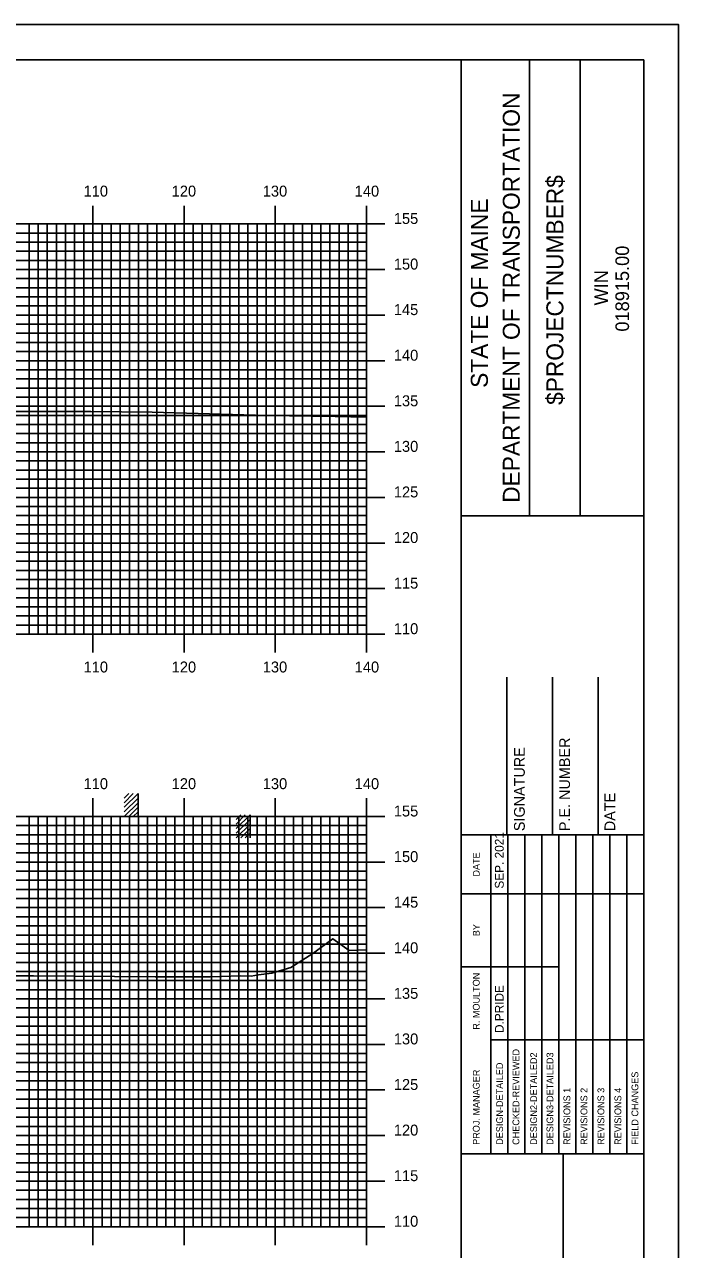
# Model space of a CAD drawing. Extents: x 1770448 to 1770792, y 442591 to 442811.
# Drawn here: x 1770716.5 to 1770788.3, y 442676.2 to 442810.5 of the extents above; entities that cross this region are included whole.
import ezdxf

# ---------------------------------------------------------------- set-up
doc = ezdxf.new("R2010")
doc.units = 0
for name, color, linetype in [('BORDER', 7, 'Continuous'), ('H_V ANNOTATION', 7, 'Continuous'), ('M_Buildings_Rooftop', 7, 'Continuous'), ('MAJOR', 7, 'Continuous'), ('MINOR', 7, 'Continuous'), ('PLOT BOUNDARY', 7, 'Continuous'), ('S_Roadway_Centerline', 7, 'Continuous')]:
    doc.layers.add(name, color=color, linetype=linetype)

msp = doc.modelspace()

# ---------------------------------------------------------------- linework, layer by layer
at = {"layer": 'BORDER'}
for p, q in [((1770764.44, 442596.67), (1770764.44, 442806.67)), ((1770771.9, 442756.66), (1770771.9, 442806.66)), ((1770777.49, 442756.66), (1770777.49, 442806.66)), ((1770764.44, 442756.65), (1770784.44, 442756.65)), ((1770769.44, 442721.67), (1770769.44, 442738.97)), ((1770774.44, 442721.67), (1770774.44, 442738.97)), ((1770779.44, 442721.67), (1770779.44, 442738.97)), ((1770764.44, 442721.67), (1770784.44, 442721.67)), ((1770764.44, 442686.67), (1770784.44, 442686.67)), ((1770775.62, 442616.67), (1770775.62, 442686.67))]:
    msp.add_line(p, q, dxfattribs=at)
msp.add_lwpolyline([(1770464.44, 442596.67), (1770784.44, 442596.67), (1770784.44, 442806.67), (1770464.44, 442806.67)], close=True, dxfattribs=at)
for points in [[(1770767.67, 442715.17), (1770767.67, 442721.67)], [(1770769.54, 442686.68), (1770769.54, 442721.67)], [(1770771.4, 442721.67), (1770771.4, 442686.68)], [(1770773.26, 442686.68), (1770773.26, 442721.67)], [(1770775.13, 442686.68), (1770775.13, 442721.67)], [(1770776.99, 442686.68), (1770776.99, 442721.67)], [(1770778.85, 442686.68), (1770778.85, 442721.67)], [(1770780.72, 442686.68), (1770780.72, 442721.67)], [(1770782.58, 442686.68), (1770782.58, 442721.67)], [(1770767.67, 442686.68), (1770767.67, 442720.26)], [(1770764.44, 442715.17), (1770784.44, 442715.17)], [(1770764.44, 442707.17), (1770767.67, 442707.17)], [(1770767.67, 442707.17), (1770775.12, 442707.17)], [(1770767.67, 442699.17), (1770784.44, 442699.17)]]:
    msp.add_lwpolyline(points, dxfattribs=at)
at = {"layer": 'M_Buildings_Rooftop'}
for p, q in [((1770727.48, 442724.68), (1770728.99, 442726.19)), ((1770727.48, 442725.17), (1770728.47, 442726.19)), ((1770727.48, 442725.67), (1770727.97, 442726.19)), ((1770728.99, 442723.67), (1770728.99, 442726.19)), ((1770727.48, 442724.19), (1770728.99, 442725.67)), ((1770727.48, 442723.67), (1770728.99, 442725.17)), ((1770727.97, 442723.67), (1770728.99, 442724.68)), ((1770728.47, 442723.67), (1770728.99, 442724.19)), ((1770739.76, 442722.34), (1770741.27, 442723.85)), ((1770739.76, 442722.84), (1770740.75, 442723.85)), ((1770739.76, 442723.33), (1770740.26, 442723.85)), ((1770739.76, 442721.85), (1770741.27, 442723.33)), ((1770741.27, 442721.33), (1770741.27, 442723.85)), ((1770739.76, 442721.33), (1770741.27, 442722.84)), ((1770740.26, 442721.33), (1770741.27, 442722.34)), ((1770740.75, 442721.33), (1770741.27, 442721.85))]:
    msp.add_line(p, q, dxfattribs=at)
at = {"layer": 'MAJOR'}
for p, q in [((1770724.04, 442790.67), (1770724.04, 442788.67)), ((1770734.04, 442790.67), (1770734.04, 442788.67)), ((1770744.04, 442790.67), (1770744.04, 442788.67)), ((1770754.04, 442790.67), (1770754.04, 442788.67)), ((1770474.04, 442788.67), (1770754.04, 442788.67)), ((1770474.04, 442788.67), (1770754.04, 442788.67)), ((1770724.04, 442743.67), (1770724.04, 442788.67)), ((1770734.04, 442743.67), (1770734.04, 442788.67)), ((1770744.04, 442743.67), (1770744.04, 442788.67)), ((1770756.05, 442788.67), (1770752.04, 442788.67)), ((1770754.04, 442743.67), (1770754.04, 442788.67)), ((1770754.04, 442743.67), (1770754.04, 442788.67)), ((1770474.04, 442783.67), (1770754.04, 442783.67)), ((1770756.05, 442783.67), (1770752.04, 442783.67)), ((1770474.04, 442778.67), (1770754.04, 442778.67)), ((1770756.05, 442778.67), (1770752.04, 442778.67)), ((1770474.04, 442773.67), (1770754.04, 442773.67)), ((1770756.05, 442773.67), (1770752.04, 442773.67)), ((1770474.04, 442768.67), (1770754.04, 442768.67)), ((1770756.05, 442768.67), (1770752.04, 442768.67)), ((1770474.04, 442763.67), (1770754.04, 442763.67)), ((1770756.05, 442763.67), (1770752.04, 442763.67)), ((1770474.04, 442758.67), (1770754.04, 442758.67)), ((1770756.05, 442758.67), (1770752.04, 442758.67)), ((1770474.04, 442753.67), (1770754.04, 442753.67)), ((1770756.05, 442753.67), (1770752.04, 442753.67)), ((1770474.04, 442748.67), (1770754.04, 442748.67)), ((1770756.05, 442748.67), (1770752.04, 442748.67)), ((1770474.04, 442743.67), (1770754.04, 442743.67)), ((1770474.04, 442743.67), (1770754.04, 442743.67)), ((1770724.04, 442741.66), (1770724.04, 442743.67)), ((1770734.04, 442741.66), (1770734.04, 442743.67)), ((1770744.04, 442741.66), (1770744.04, 442743.67)), ((1770756.05, 442743.67), (1770752.04, 442743.67)), ((1770754.04, 442741.66), (1770754.04, 442743.67)), ((1770724.04, 442725.67), (1770724.04, 442723.67)), ((1770734.04, 442725.67), (1770734.04, 442723.67)), ((1770744.04, 442725.67), (1770744.04, 442723.67)), ((1770754.04, 442725.67), (1770754.04, 442723.67)), ((1770474.04, 442723.67), (1770754.04, 442723.67)), ((1770474.04, 442723.67), (1770754.04, 442723.67)), ((1770724.04, 442678.67), (1770724.04, 442723.67)), ((1770734.04, 442678.67), (1770734.04, 442723.67)), ((1770744.04, 442678.67), (1770744.04, 442723.67)), ((1770756.05, 442723.67), (1770752.04, 442723.67)), ((1770754.04, 442678.67), (1770754.04, 442723.67)), ((1770754.04, 442678.67), (1770754.04, 442723.67)), ((1770474.04, 442718.67), (1770754.04, 442718.67)), ((1770756.05, 442718.67), (1770752.04, 442718.67)), ((1770474.04, 442713.67), (1770754.04, 442713.67)), ((1770756.05, 442713.67), (1770752.04, 442713.67)), ((1770474.04, 442708.67), (1770754.04, 442708.67)), ((1770756.05, 442708.67), (1770752.04, 442708.67)), ((1770474.04, 442703.67), (1770754.04, 442703.67)), ((1770756.05, 442703.67), (1770752.04, 442703.67)), ((1770474.04, 442698.67), (1770754.04, 442698.67)), ((1770756.05, 442698.67), (1770752.04, 442698.67)), ((1770474.04, 442693.67), (1770754.04, 442693.67)), ((1770756.05, 442693.67), (1770752.04, 442693.67)), ((1770474.04, 442688.67), (1770754.04, 442688.67)), ((1770756.05, 442688.67), (1770752.04, 442688.67)), ((1770474.04, 442683.67), (1770754.04, 442683.67)), ((1770756.05, 442683.67), (1770752.04, 442683.67)), ((1770474.04, 442678.67), (1770754.04, 442678.67)), ((1770474.04, 442678.67), (1770754.04, 442678.67)), ((1770724.04, 442676.66), (1770724.04, 442678.67)), ((1770734.04, 442676.66), (1770734.04, 442678.67)), ((1770744.04, 442676.66), (1770744.04, 442678.67)), ((1770756.05, 442678.67), (1770752.04, 442678.67)), ((1770754.04, 442676.66), (1770754.04, 442678.67))]:
    msp.add_line(p, q, dxfattribs=at)
at = {"layer": 'MINOR'}
for p, q in [((1770717.04, 442743.67), (1770717.04, 442788.67)), ((1770718.04, 442743.67), (1770718.04, 442788.67)), ((1770719.04, 442743.67), (1770719.04, 442788.67)), ((1770720.04, 442743.67), (1770720.04, 442788.67)), ((1770721.04, 442743.67), (1770721.04, 442788.67)), ((1770722.04, 442743.67), (1770722.04, 442788.67)), ((1770723.04, 442743.67), (1770723.04, 442788.67)), ((1770725.04, 442743.67), (1770725.04, 442788.67)), ((1770726.04, 442743.67), (1770726.04, 442788.67)), ((1770727.04, 442743.67), (1770727.04, 442788.67)), ((1770728.04, 442743.67), (1770728.04, 442788.67)), ((1770729.04, 442743.67), (1770729.04, 442788.67)), ((1770730.04, 442743.67), (1770730.04, 442788.67)), ((1770731.04, 442743.67), (1770731.04, 442788.67)), ((1770732.04, 442743.67), (1770732.04, 442788.67)), ((1770733.04, 442743.67), (1770733.04, 442788.67)), ((1770735.04, 442743.67), (1770735.04, 442788.67)), ((1770736.04, 442743.67), (1770736.04, 442788.67)), ((1770737.04, 442743.67), (1770737.04, 442788.67)), ((1770738.04, 442743.67), (1770738.04, 442788.67)), ((1770739.04, 442743.67), (1770739.04, 442788.67)), ((1770740.04, 442743.67), (1770740.04, 442788.67)), ((1770741.04, 442743.67), (1770741.04, 442788.67)), ((1770742.04, 442743.67), (1770742.04, 442788.67)), ((1770743.04, 442743.67), (1770743.04, 442788.67)), ((1770745.04, 442743.67), (1770745.04, 442788.67)), ((1770746.04, 442743.67), (1770746.04, 442788.67)), ((1770747.04, 442743.67), (1770747.04, 442788.67)), ((1770748.04, 442743.67), (1770748.04, 442788.67)), ((1770749.04, 442743.67), (1770749.04, 442788.67)), ((1770750.04, 442743.67), (1770750.04, 442788.67)), ((1770751.04, 442743.67), (1770751.04, 442788.67)), ((1770752.04, 442743.67), (1770752.04, 442788.67)), ((1770753.04, 442743.67), (1770753.04, 442788.67)), ((1770474.04, 442787.67), (1770754.04, 442787.67)), ((1770474.04, 442786.67), (1770754.04, 442786.67)), ((1770754.04, 442787.67), (1770752.04, 442787.67)), ((1770754.04, 442786.67), (1770752.04, 442786.67)), ((1770474.04, 442785.67), (1770754.04, 442785.67)), ((1770754.04, 442785.67), (1770752.04, 442785.67)), ((1770474.04, 442784.67), (1770754.04, 442784.67)), ((1770754.04, 442784.67), (1770752.04, 442784.67)), ((1770474.04, 442782.67), (1770754.04, 442782.67)), ((1770754.04, 442782.67), (1770752.04, 442782.67)), ((1770474.04, 442781.67), (1770754.04, 442781.67)), ((1770754.04, 442781.67), (1770752.04, 442781.67)), ((1770474.04, 442780.67), (1770754.04, 442780.67)), ((1770474.04, 442779.67), (1770754.04, 442779.67)), ((1770754.04, 442780.67), (1770752.04, 442780.67)), ((1770754.04, 442779.67), (1770752.04, 442779.67)), ((1770474.04, 442777.67), (1770754.04, 442777.67)), ((1770754.04, 442777.67), (1770752.04, 442777.67)), ((1770474.04, 442776.67), (1770754.04, 442776.67)), ((1770474.04, 442775.67), (1770754.04, 442775.67)), ((1770754.04, 442776.67), (1770752.04, 442776.67)), ((1770754.04, 442775.67), (1770752.04, 442775.67)), ((1770474.04, 442774.67), (1770754.04, 442774.67)), ((1770754.04, 442774.67), (1770752.04, 442774.67)), ((1770474.04, 442772.67), (1770754.04, 442772.67)), ((1770474.04, 442771.67), (1770754.04, 442771.67)), ((1770754.04, 442772.67), (1770752.04, 442772.67)), ((1770754.04, 442771.67), (1770752.04, 442771.67)), ((1770474.04, 442770.67), (1770754.04, 442770.67)), ((1770754.04, 442770.67), (1770752.04, 442770.67)), ((1770474.04, 442769.67), (1770754.04, 442769.67)), ((1770754.04, 442769.67), (1770752.04, 442769.67)), ((1770474.04, 442767.67), (1770754.04, 442767.67)), ((1770754.04, 442767.67), (1770752.04, 442767.67)), ((1770474.04, 442766.67), (1770754.04, 442766.67)), ((1770754.04, 442766.67), (1770752.04, 442766.67)), ((1770474.04, 442765.67), (1770754.04, 442765.67)), ((1770754.04, 442765.67), (1770752.04, 442765.67)), ((1770474.04, 442764.67), (1770754.04, 442764.67)), ((1770754.04, 442764.67), (1770752.04, 442764.67)), ((1770474.04, 442762.67), (1770754.04, 442762.67)), ((1770754.04, 442762.67), (1770752.04, 442762.67)), ((1770474.04, 442761.67), (1770754.04, 442761.67)), ((1770754.04, 442761.67), (1770752.04, 442761.67)), ((1770474.04, 442760.67), (1770754.04, 442760.67)), ((1770474.04, 442759.67), (1770754.04, 442759.67)), ((1770754.04, 442760.67), (1770752.04, 442760.67)), ((1770754.04, 442759.67), (1770752.04, 442759.67)), ((1770474.04, 442757.67), (1770754.04, 442757.67)), ((1770754.04, 442757.67), (1770752.04, 442757.67)), ((1770474.04, 442756.67), (1770754.04, 442756.67)), ((1770474.04, 442755.67), (1770754.04, 442755.67)), ((1770754.04, 442756.67), (1770752.04, 442756.67)), ((1770754.04, 442755.67), (1770752.04, 442755.67)), ((1770474.04, 442754.67), (1770754.04, 442754.67)), ((1770754.04, 442754.67), (1770752.04, 442754.67)), ((1770474.04, 442752.67), (1770754.04, 442752.67)), ((1770474.04, 442751.67), (1770754.04, 442751.67)), ((1770754.04, 442752.67), (1770752.04, 442752.67)), ((1770754.04, 442751.67), (1770752.04, 442751.67)), ((1770474.04, 442750.67), (1770754.04, 442750.67)), ((1770754.04, 442750.67), (1770752.04, 442750.67)), ((1770474.04, 442749.67), (1770754.04, 442749.67)), ((1770754.04, 442749.67), (1770752.04, 442749.67)), ((1770474.04, 442747.67), (1770754.04, 442747.67)), ((1770754.04, 442747.67), (1770752.04, 442747.67)), ((1770474.04, 442746.67), (1770754.04, 442746.67)), ((1770754.04, 442746.67), (1770752.04, 442746.67)), ((1770474.04, 442745.67), (1770754.04, 442745.67)), ((1770754.04, 442745.67), (1770752.04, 442745.67)), ((1770474.04, 442744.67), (1770754.04, 442744.67)), ((1770754.04, 442744.67), (1770752.04, 442744.67)), ((1770717.04, 442678.67), (1770717.04, 442723.67)), ((1770718.04, 442678.67), (1770718.04, 442723.67)), ((1770719.04, 442678.67), (1770719.04, 442723.67)), ((1770720.04, 442678.67), (1770720.04, 442723.67)), ((1770721.04, 442678.67), (1770721.04, 442723.67)), ((1770722.04, 442678.67), (1770722.04, 442723.67)), ((1770723.04, 442678.67), (1770723.04, 442723.67)), ((1770725.04, 442678.67), (1770725.04, 442723.67)), ((1770726.04, 442678.67), (1770726.04, 442723.67)), ((1770727.04, 442678.67), (1770727.04, 442723.67)), ((1770728.04, 442678.67), (1770728.04, 442723.67)), ((1770729.04, 442678.67), (1770729.04, 442723.67)), ((1770730.04, 442678.67), (1770730.04, 442723.67)), ((1770731.04, 442678.67), (1770731.04, 442723.67)), ((1770732.04, 442678.67), (1770732.04, 442723.67)), ((1770733.04, 442678.67), (1770733.04, 442723.67)), ((1770735.04, 442678.67), (1770735.04, 442723.67)), ((1770736.04, 442678.67), (1770736.04, 442723.67)), ((1770737.04, 442678.67), (1770737.04, 442723.67)), ((1770738.04, 442678.67), (1770738.04, 442723.67)), ((1770739.04, 442678.67), (1770739.04, 442723.67)), ((1770740.04, 442678.67), (1770740.04, 442723.67)), ((1770741.04, 442678.67), (1770741.04, 442723.67)), ((1770742.04, 442678.67), (1770742.04, 442723.67)), ((1770743.04, 442678.67), (1770743.04, 442723.67)), ((1770745.04, 442678.67), (1770745.04, 442723.67)), ((1770746.04, 442678.67), (1770746.04, 442723.67)), ((1770747.04, 442678.67), (1770747.04, 442723.67)), ((1770748.04, 442678.67), (1770748.04, 442723.67)), ((1770749.04, 442678.67), (1770749.04, 442723.67)), ((1770750.04, 442678.67), (1770750.04, 442723.67)), ((1770751.04, 442678.67), (1770751.04, 442723.67)), ((1770752.04, 442678.67), (1770752.04, 442723.67)), ((1770753.04, 442678.67), (1770753.04, 442723.67)), ((1770474.04, 442722.67), (1770754.04, 442722.67)), ((1770754.04, 442722.67), (1770752.04, 442722.67)), ((1770474.04, 442721.67), (1770754.04, 442721.67)), ((1770474.04, 442720.67), (1770754.04, 442720.67)), ((1770754.04, 442721.67), (1770752.04, 442721.67)), ((1770754.04, 442720.67), (1770752.04, 442720.67)), ((1770474.04, 442719.67), (1770754.04, 442719.67)), ((1770754.04, 442719.67), (1770752.04, 442719.67)), ((1770474.04, 442717.67), (1770754.04, 442717.67)), ((1770474.04, 442716.67), (1770754.04, 442716.67)), ((1770754.04, 442717.67), (1770752.04, 442717.67)), ((1770754.04, 442716.67), (1770752.04, 442716.67)), ((1770474.04, 442715.67), (1770754.04, 442715.67)), ((1770754.04, 442715.67), (1770752.04, 442715.67)), ((1770474.04, 442714.67), (1770754.04, 442714.67)), ((1770754.04, 442714.67), (1770752.04, 442714.67)), ((1770474.04, 442712.67), (1770754.04, 442712.67)), ((1770754.04, 442712.67), (1770752.04, 442712.67)), ((1770474.04, 442711.67), (1770754.04, 442711.67)), ((1770754.04, 442711.67), (1770752.04, 442711.67)), ((1770474.04, 442710.67), (1770754.04, 442710.67)), ((1770754.04, 442710.67), (1770752.04, 442710.67)), ((1770474.04, 442709.67), (1770754.04, 442709.67)), ((1770754.04, 442709.67), (1770752.04, 442709.67)), ((1770474.04, 442707.67), (1770754.04, 442707.67)), ((1770754.04, 442707.67), (1770752.04, 442707.67)), ((1770474.04, 442706.67), (1770754.04, 442706.67)), ((1770754.04, 442706.67), (1770752.04, 442706.67)), ((1770474.04, 442705.67), (1770754.04, 442705.67)), ((1770474.04, 442704.67), (1770754.04, 442704.67)), ((1770754.04, 442705.67), (1770752.04, 442705.67)), ((1770754.04, 442704.67), (1770752.04, 442704.67)), ((1770474.04, 442702.67), (1770754.04, 442702.67)), ((1770754.04, 442702.67), (1770752.04, 442702.67)), ((1770474.04, 442701.67), (1770754.04, 442701.67)), ((1770474.04, 442700.67), (1770754.04, 442700.67)), ((1770754.04, 442701.67), (1770752.04, 442701.67)), ((1770754.04, 442700.67), (1770752.04, 442700.67)), ((1770474.04, 442699.67), (1770754.04, 442699.67)), ((1770754.04, 442699.67), (1770752.04, 442699.67)), ((1770474.04, 442697.67), (1770754.04, 442697.67)), ((1770474.04, 442696.67), (1770754.04, 442696.67)), ((1770754.04, 442697.67), (1770752.04, 442697.67)), ((1770754.04, 442696.67), (1770752.04, 442696.67)), ((1770474.04, 442695.67), (1770754.04, 442695.67)), ((1770754.04, 442695.67), (1770752.04, 442695.67)), ((1770474.04, 442694.67), (1770754.04, 442694.67)), ((1770754.04, 442694.67), (1770752.04, 442694.67)), ((1770474.04, 442692.67), (1770754.04, 442692.67)), ((1770754.04, 442692.67), (1770752.04, 442692.67)), ((1770474.04, 442691.67), (1770754.04, 442691.67)), ((1770754.04, 442691.67), (1770752.04, 442691.67)), ((1770474.04, 442690.67), (1770754.04, 442690.67)), ((1770474.04, 442689.67), (1770754.04, 442689.67)), ((1770754.04, 442690.67), (1770752.04, 442690.67)), ((1770754.04, 442689.67), (1770752.04, 442689.67)), ((1770474.04, 442687.67), (1770754.04, 442687.67)), ((1770754.04, 442687.67), (1770752.04, 442687.67)), ((1770474.04, 442686.67), (1770754.04, 442686.67)), ((1770474.04, 442685.67), (1770754.04, 442685.67)), ((1770754.04, 442686.67), (1770752.04, 442686.67)), ((1770754.04, 442685.67), (1770752.04, 442685.67)), ((1770474.04, 442684.67), (1770754.04, 442684.67)), ((1770754.04, 442684.67), (1770752.04, 442684.67)), ((1770474.04, 442682.67), (1770754.04, 442682.67)), ((1770474.04, 442681.67), (1770754.04, 442681.67)), ((1770754.04, 442682.67), (1770752.04, 442682.67)), ((1770754.04, 442681.67), (1770752.04, 442681.67)), ((1770474.04, 442680.67), (1770754.04, 442680.67)), ((1770754.04, 442680.67), (1770752.04, 442680.67)), ((1770474.04, 442679.67), (1770754.04, 442679.67)), ((1770754.04, 442679.67), (1770752.04, 442679.67))]:
    msp.add_line(p, q, dxfattribs=at)
at = {"layer": 'PLOT BOUNDARY'}
msp.add_lwpolyline([(1770448.25, 442590.55), (1770788.25, 442590.55), (1770788.25, 442810.55), (1770448.25, 442810.55)], close=True, dxfattribs=at)
at = {"layer": 'S_Roadway_Centerline'}
for points in [[(1770632.95, 442771.24), (1770647.41, 442770.43), (1770651.01, 442770.28), (1770653.21, 442770.17), (1770664.83, 442769.78), (1770672.2, 442769.43), (1770676.05, 442769.26), (1770682.44, 442769.03), (1770688.99, 442768.74), (1770692.16, 442768.52), (1770701.49, 442768.35), (1770702.57, 442768.34), (1770710.75, 442768.14), (1770711.11, 442768.14), (1770711.48, 442768.17), (1770711.76, 442768.17), (1770712.08, 442768.16), (1770712.32, 442768.14), (1770713.52, 442768.09), (1770723.83, 442768.1), (1770730.53, 442768.04), (1770743.12, 442767.64), (1770750.6, 442767.55), (1770754.04, 442767.48)], [(1770710.81, 442706.18), (1770717.51, 442706.19), (1770730.88, 442706.08), (1770732.83, 442706.1), (1770736.89, 442706.07), (1770738.15, 442706.11), (1770740.24, 442706.2), (1770741.38, 442706.14), (1770742.21, 442706.29), (1770743.67, 442706.49), (1770745.75, 442707.1), (1770748.16, 442708.64), (1770750.35, 442710.26), (1770752.13, 442708.98), (1770754.04, 442709.04)]]:
    msp.add_lwpolyline(points, dxfattribs=at)

# ---------------------------------------------------------------- texts
at = {"layer": 'BORDER'}
for s, height, p in [('DEPARTMENT OF TRANSPORTATION', 1.8635, (1770770.85, 442758.08)), ('$PROJECTNUMBER$', 1.8635, (1770775.63, 442768.82)), ('STATE OF MAINE', 1.8635, (1770767.35, 442770.69)), ('018915.00', 1.491, (1770782.83, 442776.86)), ('WIN', 1.491, (1770780.51, 442779.73)), ('P.E. NUMBER', 1.1811, (1770776.36, 442722.06)), ('SIGNATURE', 1.181, (1770771.4, 442722.06)), ('DATE', 1.181, (1770781.32, 442722.06)), ('SEP. 2021', 0.969, (1770769.09, 442715.76)), ('DATE', 0.743, (1770766.45, 442717.08)), ('BY', 0.743, (1770766.45, 442710.54)), ('R. MOULTON', 0.745, (1770766.45, 442700.28)), ('D.PRIDE', 0.969, (1770769.09, 442699.92)), ('CHECKED-REVIEWED', 0.7455, (1770770.8, 442687.65)), ('DESIGN2-DETAILED2', 0.7455, (1770772.74, 442687.65)), ('DESIGN3-DETAILED3', 0.7455, (1770774.53, 442687.65)), ('DESIGN-DETAILED', 0.7455, (1770769.01, 442687.65)), ('PROJ. MANAGER', 0.7455, (1770766.45, 442687.65)), ('FIELD CHANGES', 0.7455, (1770783.85, 442687.65)), ('REVISIONS 1', 0.7455, (1770776.39, 442687.65)), ('REVISIONS 2', 0.7455, (1770778.26, 442687.65)), ('REVISIONS 3', 0.7455, (1770780.12, 442687.65)), ('REVISIONS 4', 0.7455, (1770781.98, 442687.65))]:
    msp.add_text(s, height=height, rotation=90, dxfattribs=at).set_placement(p)
at = {"layer": 'H_V ANNOTATION'}
for s, p in [('110', (1770723.02, 442791.67)), ('120', (1770732.68, 442791.67)), ('130', (1770742.67, 442791.67)), ('140', (1770752.75, 442791.67)), ('155', (1770757.04, 442788.67)), ('150', (1770757.04, 442783.67)), ('145', (1770757.04, 442778.67)), ('140', (1770757.04, 442773.67)), ('135', (1770757.04, 442768.67)), ('130', (1770757.04, 442763.67)), ('125', (1770757.04, 442758.67)), ('120', (1770757.04, 442753.67)), ('115', (1770757.04, 442748.67)), ('110', (1770757.04, 442743.67)), ('110', (1770723.02, 442739.47)), ('120', (1770732.68, 442739.47)), ('130', (1770742.67, 442739.47)), ('140', (1770752.75, 442739.47)), ('110', (1770723.02, 442726.67)), ('120', (1770732.68, 442726.67)), ('130', (1770742.67, 442726.67)), ('140', (1770752.75, 442726.67)), ('155', (1770757.04, 442723.67)), ('150', (1770757.04, 442718.67)), ('145', (1770757.04, 442713.67)), ('140', (1770757.04, 442708.67)), ('135', (1770757.04, 442703.67)), ('130', (1770757.04, 442698.67)), ('125', (1770757.04, 442693.67)), ('120', (1770757.04, 442688.67)), ('115', (1770757.04, 442683.67)), ('110', (1770757.04, 442678.67))]:
    msp.add_text(s, height=1.2, dxfattribs=at).set_placement(p)

doc.saveas('drawing.dxf')
